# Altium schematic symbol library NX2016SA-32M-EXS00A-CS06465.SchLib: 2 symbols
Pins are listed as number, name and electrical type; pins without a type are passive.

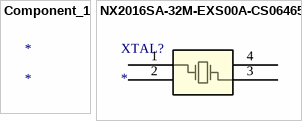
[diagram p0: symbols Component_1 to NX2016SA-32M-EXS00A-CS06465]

## Component_1
designator *

## NX2016SA-32M-EXS00A-CS06465
designator XTAL?
No Description Available; Mfr_Name: NDK
footprint NX2016SA_NDK
pins: 1, 2, 3, 4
